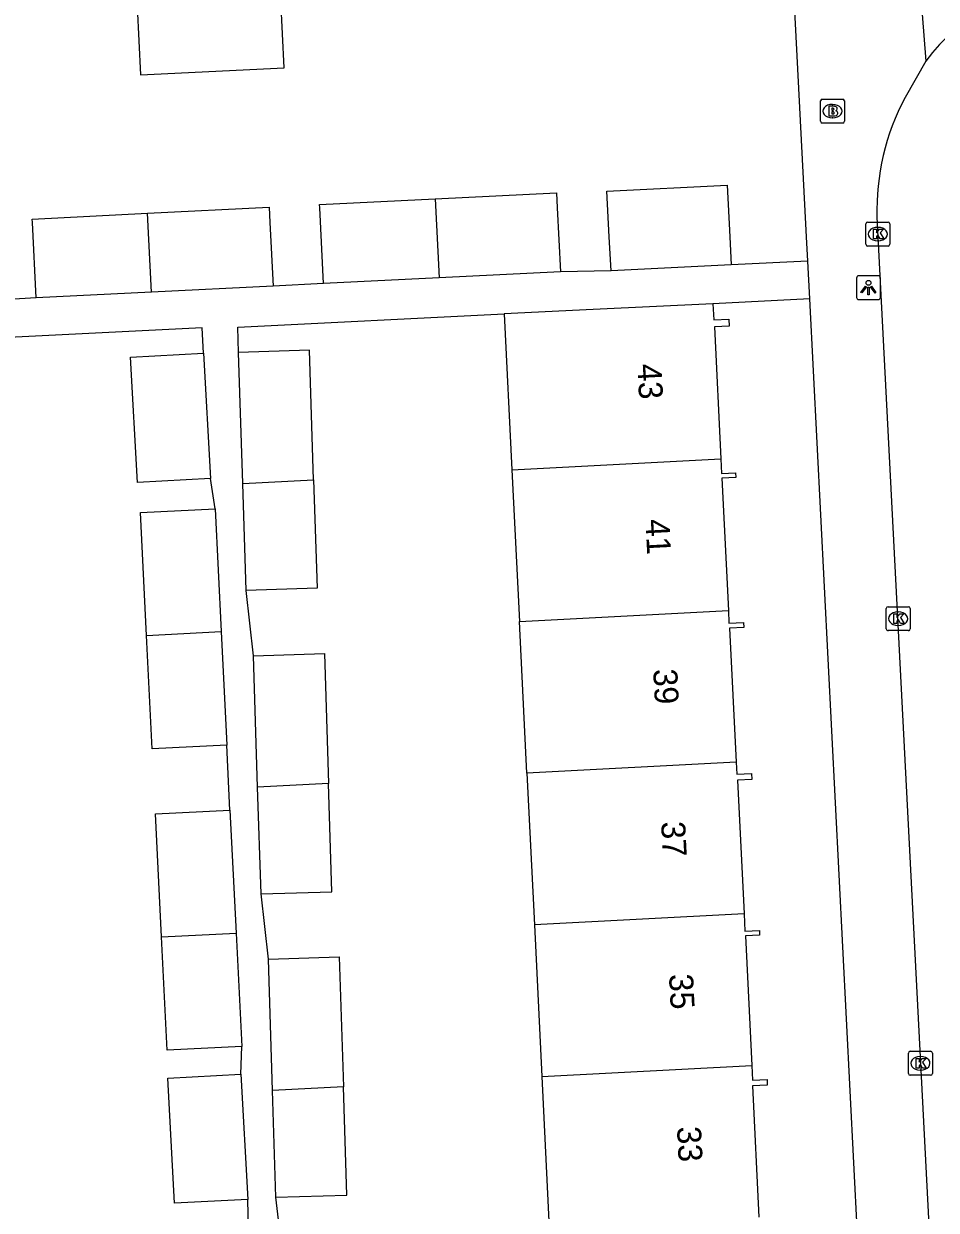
# Model space of a CAD drawing. Extents: x 161084 to 161928, y 385355 to 386522.
# Drawn here: x 161432.14 to 161470.21, y 385959.37 to 386008.9 of the extents above; entities that cross this region are included whole.
import ezdxf

# ---------------------------------------------------------------- set-up
doc = ezdxf.new("R2010")
doc.units = 0
for name, color, linetype in [('IMGEO_Brandkraan', 7, 'Continuous'), ('IMGEO_Kolk', 7, 'Continuous'), ('IMGEO_Lichtpunt', 7, 'Continuous'), ('IMGEO_Pand', 7, 'Continuous'), ('IMGEO_Pand_nummerreeks', 7, 'Continuous'), ('IMGEO_Rijbaan_lokaal_open', 7, 'Continuous'), ('IMGEO_Voetpad_open', 7, 'Continuous')]:
    doc.layers.add(name, color=color, linetype=linetype)

msp = doc.modelspace()

# ---------------------------------------------------------------- linework, layer by layer
at = {"layer": 'IMGEO_Brandkraan'}
for p, q in [((161465.459, 386005.754), (161466.311, 386005.754)), ((161465.384, 386004.828), (161465.384, 386005.68)), ((161465.872, 386005.534), (161465.897, 386005.534)), ((161466.385, 386005.68), (161466.385, 386004.828)), ((161466.311, 386004.754), (161465.459, 386004.754)), ((161465.895, 386004.974), (161465.87, 386004.974))]:
    msp.add_line(p, q, dxfattribs=at)
for points in [[(161465.459, 386005.754), (161466.311, 386005.754)], [(161465.384, 386004.828), (161465.384, 386005.68)], [(161465.732, 386005.454), (161465.732, 386005.054), (161465.945, 386005.054)], [(161465.963, 386005.454), (161465.732, 386005.454)], [(161465.911, 386005.373), (161465.857, 386005.373), (161465.857, 386005.297)], [(161465.857, 386005.297), (161465.91, 386005.297)], [(161465.919, 386005.221), (161465.857, 386005.221), (161465.857, 386005.14)], [(161466.385, 386005.68), (161466.385, 386004.828)], [(161466.311, 386004.754), (161465.459, 386004.754)], [(161465.857, 386005.14), (161465.919, 386005.14)]]:
    msp.add_lwpolyline(points, dxfattribs=at)
for centre, radius, start, end in [((161465.461, 386005.678), 0.0765, 91.552, 178.448), ((161465.461, 386005.678), 0.0765, 91.552, 178.448), ((161466.309, 386005.678), 0.0765, 1.552, 88.448), ((161466.309, 386005.678), 0.0765, 1.552, 88.448), ((161465.912, 386005.335), 0.0379, 267.8285, 90.9355), ((161465.92, 386005.18), 0.0404, 269.8759, 90.5077), ((161465.967, 386005.309), 0.145, 59.4692, 91.5367), ((161465.992, 386005.356), 0.0922, 285.5137, 58.1501), ((161465.997, 386005.164), 0.105, 301.3115, 78.989), ((161465.461, 386004.83), 0.0765, 181.552, 268.448), ((161465.461, 386004.83), 0.0765, 181.552, 268.448), ((161465.951, 386005.305), 0.251, 268.6676, 293.5347), ((161466.309, 386004.83), 0.0765, 271.552, 358.448), ((161466.309, 386004.83), 0.0765, 271.552, 358.448)]:
    msp.add_arc(centre, radius, start, end, dxfattribs=at)
for centre, major_axis, ratio, start_param, end_param in [((161465.871, 386005.254), (-0.387, 0.002), 0.722429, 4.712389, 7.853982), ((161465.896, 386005.254), (-0.39, 0.002), 0.717154, 1.570796, 4.712389)]:
    msp.add_ellipse(centre, major_axis=major_axis, ratio=ratio, start_param=start_param, end_param=end_param, dxfattribs=at)
at = {"layer": 'IMGEO_Kolk'}
for p, q in [((161467.274, 385999.695), (161467.274, 386000.547)), ((161467.349, 386000.621), (161468.201, 386000.621)), ((161467.762, 386000.401), (161467.787, 386000.401)), ((161468.275, 386000.547), (161468.275, 385999.695)), ((161467.785, 385999.841), (161467.76, 385999.841)), ((161468.201, 385999.621), (161467.349, 385999.621)), ((161468.126, 385983.638), (161468.126, 385984.49)), ((161468.201, 385984.564), (161469.053, 385984.564)), ((161469.127, 385984.49), (161469.127, 385983.638)), ((161468.614, 385984.344), (161468.639, 385984.344)), ((161469.053, 385983.564), (161468.201, 385983.564)), ((161468.637, 385983.784), (161468.612, 385983.784)), ((161469.049, 385965.076), (161469.049, 385965.928)), ((161469.124, 385966.002), (161469.976, 385966.002)), ((161469.537, 385965.782), (161469.562, 385965.782)), ((161470.05, 385965.928), (161470.05, 385965.076)), ((161469.56, 385965.222), (161469.535, 385965.222)), ((161469.976, 385965.002), (161469.124, 385965.002))]:
    msp.add_line(p, q, dxfattribs=at)
for points in [[(161467.274, 385999.695), (161467.274, 386000.547)], [(161467.349, 386000.621), (161468.201, 386000.621)], [(161467.595, 386000.321), (161467.718, 386000.321), (161467.718, 386000.17), (161467.848, 386000.321), (161468.012, 386000.321), (161467.866, 386000.17), (161468.019, 385999.921), (161467.867, 385999.921), (161467.782, 386000.085), (161467.718, 386000.018), (161467.718, 385999.921), (161467.595, 385999.921), (161467.595, 386000.321)], [(161468.275, 386000.547), (161468.275, 385999.695)], [(161468.201, 385999.621), (161467.349, 385999.621)], [(161468.126, 385983.638), (161468.126, 385984.49)], [(161468.201, 385984.564), (161469.053, 385984.564)], [(161469.127, 385984.49), (161469.127, 385983.638)], [(161468.447, 385984.264), (161468.57, 385984.264), (161468.57, 385984.113), (161468.7, 385984.264), (161468.864, 385984.264), (161468.718, 385984.113), (161468.871, 385983.864), (161468.719, 385983.864), (161468.634, 385984.028), (161468.57, 385983.961), (161468.57, 385983.864), (161468.447, 385983.864), (161468.447, 385984.264)], [(161469.053, 385983.564), (161468.201, 385983.564)], [(161469.049, 385965.076), (161469.049, 385965.928)], [(161469.124, 385966.002), (161469.976, 385966.002)], [(161469.37, 385965.702), (161469.493, 385965.702), (161469.493, 385965.551), (161469.623, 385965.702), (161469.787, 385965.702), (161469.641, 385965.551), (161469.794, 385965.302), (161469.642, 385965.302), (161469.557, 385965.466), (161469.493, 385965.399), (161469.493, 385965.302), (161469.37, 385965.302), (161469.37, 385965.702)], [(161470.05, 385965.928), (161470.05, 385965.076)], [(161469.976, 385965.002), (161469.124, 385965.002)]]:
    msp.add_lwpolyline(points, dxfattribs=at)
for centre, start, end in [((161467.351, 386000.545), 91.552, 178.448), ((161467.351, 386000.545), 91.552, 178.448), ((161468.199, 386000.545), 1.552, 88.448), ((161468.199, 386000.545), 1.552, 88.448), ((161467.351, 385999.697), 181.552, 268.448), ((161467.351, 385999.697), 181.552, 268.448), ((161468.199, 385999.697), 271.552, 358.448), ((161468.199, 385999.697), 271.552, 358.448), ((161468.203, 385984.488), 91.552, 178.448), ((161468.203, 385984.488), 91.552, 178.448), ((161469.051, 385984.488), 1.552, 88.448), ((161469.051, 385984.488), 1.552, 88.448), ((161468.203, 385983.64), 181.552, 268.448), ((161468.203, 385983.64), 181.552, 268.448), ((161469.051, 385983.64), 271.552, 358.448), ((161469.051, 385983.64), 271.552, 358.448), ((161469.126, 385965.926), 91.552, 178.448), ((161469.126, 385965.926), 91.552, 178.448), ((161469.974, 385965.926), 1.552, 88.448), ((161469.974, 385965.926), 1.552, 88.448), ((161469.126, 385965.078), 181.552, 268.448), ((161469.126, 385965.078), 181.552, 268.448), ((161469.974, 385965.078), 271.552, 358.448), ((161469.974, 385965.078), 271.552, 358.448)]:
    msp.add_arc(centre, 0.0765, start, end, dxfattribs=at)
for centre, major_axis, ratio, start_param, end_param in [((161467.761, 386000.121), (-0.387, 0.002), 0.722429, 4.712389, 7.853982), ((161467.786, 386000.121), (-0.39, 0.002), 0.717154, 1.570796, 4.712389), ((161468.613, 385984.064), (-0.387, 0.002), 0.722429, 4.712389, 7.853982), ((161468.638, 385984.064), (-0.39, 0.002), 0.717154, 1.570796, 4.712389), ((161469.536, 385965.502), (-0.387, 0.002), 0.722429, 4.712389, 7.853982), ((161469.561, 385965.502), (-0.39, 0.002), 0.717154, 1.570796, 4.712389)]:
    msp.add_ellipse(centre, major_axis=major_axis, ratio=ratio, start_param=start_param, end_param=end_param, dxfattribs=at)
at = {"layer": 'IMGEO_Lichtpunt'}
for p, q in [((161466.886, 385998.287), (161466.886, 385997.48)), ((161466.886, 385998.287), (161466.886, 385997.48)), ((161467.788, 385998.382), (161466.98, 385998.382)), ((161467.788, 385998.382), (161466.98, 385998.382)), ((161467.882, 385997.48), (161467.882, 385998.287)), ((161467.882, 385997.48), (161467.882, 385998.287)), ((161466.98, 385997.386), (161467.788, 385997.386)), ((161466.98, 385997.386), (161467.788, 385997.386))]:
    msp.add_line(p, q, dxfattribs=at)
for points in [[(161467.26, 385997.951), (161467.299, 385997.923), (161467.111, 385997.661), (161467.073, 385997.688), (161467.26, 385997.951)], [(161467.362, 385997.903), (161467.409, 385997.903), (161467.409, 385997.581), (161467.362, 385997.581), (161467.362, 385997.903)], [(161467.472, 385997.923), (161467.51, 385997.95), (161467.697, 385997.688), (161467.658, 385997.66), (161467.472, 385997.923)]]:
    msp.add_lwpolyline(points, dxfattribs=at)
msp.add_circle((161467.385, 385998.085), 0.0994, dxfattribs=at)
for centre, start, end in [((161466.98, 385998.287), 90, 180), ((161466.98, 385998.287), 90, 180), ((161467.788, 385998.287), 0, 90), ((161467.788, 385998.287), 0, 90), ((161466.98, 385997.48), 180, 270), ((161466.98, 385997.48), 180, 270), ((161467.788, 385997.48), 270, 0), ((161467.788, 385997.48), 270, 360)]:
    msp.add_arc(centre, 0.0946, start, end, dxfattribs=at)
at = {"layer": 'IMGEO_Pand'}
for points in [[(161436.876, 386009.607), (161437.019, 386006.766), (161443.014, 386007.068), (161442.871, 386009.909)], [(161449.302, 386001.593), (161454.367, 386001.849), (161454.4, 386001.211), (161454.54, 385998.55)], [(161456.646, 385998.584), (161456.57, 386000), (161456.467, 386001.907), (161461.487, 386002.16), (161461.596, 386000), (161461.655, 385998.831)], [(161437.312, 386000.988), (161442.376, 386001.244), (161442.409, 386000.606), (161442.549, 385997.945)], [(161444.651, 385998.061), (161444.495, 386001.211), (161444.488, 386001.35), (161449.302, 386001.593)], [(161449.302, 386001.593), (161449.468, 385998.299)], [(161432.66, 385997.456), (161432.504, 386000.606), (161432.497, 386000.745), (161437.312, 386000.988)], [(161437.479, 385997.694), (161437.312, 386000.988)], [(161461.655, 385998.831), (161456.646, 385998.584)], [(161449.468, 385998.299), (161444.651, 385998.061)], [(161454.54, 385998.55), (161449.468, 385998.299)], [(161442.549, 385997.945), (161437.479, 385997.694)], [(161437.479, 385997.694), (161432.66, 385997.456)], [(161460.895, 385997.213), (161455.902, 385996.967), (161452.193, 385996.785)], [(161452.193, 385996.785), (161452.513, 385990.284)], [(161460.895, 385997.213), (161460.928, 385996.536), (161461.561, 385996.567), (161461.575, 385996.275), (161460.957, 385996.245), (161461.228, 385990.736)], [(161439.93, 385989.915), (161436.884, 385989.751), (161436.604, 385994.98), (161439.65, 385995.143)], [(161439.65, 385995.143), (161439.93, 385989.915)], [(161444.236, 385989.855), (161444.065, 385995.275), (161441.108, 385995.182)], [(161441.281, 385989.701), (161441.108, 385995.182)], [(161452.513, 385990.284), (161461.228, 385990.736)], [(161461.228, 385990.736), (161461.258, 385990.126), (161461.841, 385990.154), (161461.851, 385989.958), (161461.268, 385989.929), (161461.54, 385984.404)], [(161441.281, 385989.701), (161444.236, 385989.855)], [(161444.236, 385989.855), (161444.379, 385985.332), (161441.422, 385985.238)], [(161452.513, 385990.284), (161452.824, 385983.952)], [(161441.422, 385985.238), (161441.281, 385989.701)], [(161437.269, 385983.369), (161437.013, 385988.499), (161440.125, 385988.655)], [(161440.125, 385988.655), (161440.381, 385983.527)], [(161452.824, 385983.952), (161461.54, 385984.404)], [(161461.54, 385984.404), (161461.566, 385983.874), (161462.172, 385983.904), (161462.183, 385983.696), (161461.59, 385983.667), (161461.865, 385978.072)], [(161453.135, 385977.619), (161452.824, 385983.952)], [(161437.269, 385983.369), (161440.381, 385983.527)], [(161440.381, 385983.527), (161440.618, 385978.789)], [(161440.618, 385978.789), (161437.506, 385978.634), (161437.269, 385983.369)], [(161441.73, 385982.517), (161444.687, 385982.61), (161444.858, 385977.19)], [(161441.903, 385977.036), (161441.73, 385982.517)], [(161461.865, 385978.072), (161453.135, 385977.619)], [(161461.865, 385978.072), (161461.89, 385977.571), (161462.51, 385977.602), (161462.522, 385977.351), (161461.919, 385977.321), (161462.193, 385971.741)], [(161453.135, 385977.619), (161453.446, 385971.288)], [(161444.858, 385977.19), (161441.903, 385977.036)], [(161442.044, 385972.573), (161441.903, 385977.036)], [(161442.044, 385972.573), (161445.001, 385972.667), (161444.858, 385977.19)], [(161437.891, 385970.784), (161437.635, 385975.915), (161440.747, 385976.071)], [(161440.747, 385976.071), (161441.003, 385970.942)], [(161462.193, 385971.741), (161453.446, 385971.288)], [(161462.193, 385971.741), (161462.229, 385971.015), (161462.834, 385971.045), (161462.844, 385970.847), (161462.248, 385970.818), (161462.514, 385965.409)], [(161453.446, 385971.288), (161453.757, 385964.955)], [(161437.891, 385970.784), (161441.003, 385970.942)], [(161441.24, 385966.205), (161438.128, 385966.05), (161437.891, 385970.784)], [(161441.003, 385970.942), (161441.24, 385966.205)], [(161442.352, 385969.853), (161445.309, 385969.946), (161445.48, 385964.526)], [(161442.525, 385964.373), (161442.352, 385969.853)], [(161453.757, 385964.955), (161462.514, 385965.409)], [(161462.514, 385965.409), (161462.544, 385964.801), (161463.153, 385964.831), (161463.165, 385964.591), (161462.547, 385964.56), (161462.817, 385959.075)], [(161441.486, 385959.821), (161438.44, 385959.658), (161438.16, 385964.886), (161441.206, 385965.049)], [(161441.206, 385965.049), (161441.486, 385959.821)], [(161453.757, 385964.955), (161454.069, 385958.622)], [(161445.48, 385964.526), (161442.525, 385964.373)], [(161442.666, 385959.909), (161442.525, 385964.373)], [(161442.666, 385959.909), (161445.623, 385960.003), (161445.48, 385964.526)]]:
    msp.add_lwpolyline(points, dxfattribs=at)
at = {"layer": 'IMGEO_Rijbaan_lokaal_open'}
for points in [[(161469.779, 386007.341), (161468.909, 386005.827)], [(161467.737, 386000.824), (161467.781, 386000), (161470.11, 385954.706)]]:
    msp.add_lwpolyline(points, dxfattribs=at)
for centre, radius, start, end in [((161475.713, 386003.075), 7.309, 88.2387, 144.287), ((161477.817, 386001.102), 10.083, 152.0542, 181.5772)]:
    msp.add_arc(centre, radius, start, end, dxfattribs=at)
at = {"layer": 'IMGEO_Voetpad_open'}
for points in [[(161464.853, 385998.993), (161464.802, 386000), (161463.668, 386021.852)], [(161469.279, 386013.763), (161469.779, 386007.341)], [(161464.853, 385998.993), (161461.655, 385998.831)], [(161464.934, 385997.415), (161464.853, 385998.993)], [(161456.646, 385998.584), (161454.54, 385998.55)], [(161444.651, 385998.061), (161442.549, 385997.945)], [(161432.66, 385997.456), (161430.557, 385997.339)], [(161464.934, 385997.415), (161460.895, 385997.213)], [(161468.916, 385919.263), (161464.934, 385997.415)], [(161441.108, 385995.182), (161441.075, 385996.239), (161452.193, 385996.785)], [(161439.65, 385995.143), (161439.593, 385996.202), (161428.165, 385995.638)], [(161440.125, 385988.655), (161439.93, 385989.915)], [(161441.73, 385982.517), (161441.422, 385985.238)], [(161440.747, 385976.071), (161440.618, 385978.789)], [(161442.352, 385969.853), (161442.044, 385972.573)], [(161441.206, 385965.049), (161441.24, 385966.205)], [(161441.619, 385954.287), (161441.486, 385959.821)], [(161442.975, 385957.188), (161442.666, 385959.909)]]:
    msp.add_lwpolyline(points, dxfattribs=at)

# ---------------------------------------------------------------- texts
at = {"layer": 'IMGEO_Pand_nummerreeks'}
for s, p in [('43', (161457.742, 385994.685)), ('41', (161458.078, 385988.204)), ('39', (161458.402, 385981.95)), ('37', (161458.732, 385975.582)), ('35', (161459.062, 385969.215)), ('33', (161459.393, 385962.847))]:
    msp.add_text(s, height=1, rotation=272.9678, dxfattribs=at).set_placement(p)

doc.saveas('drawing.dxf')
